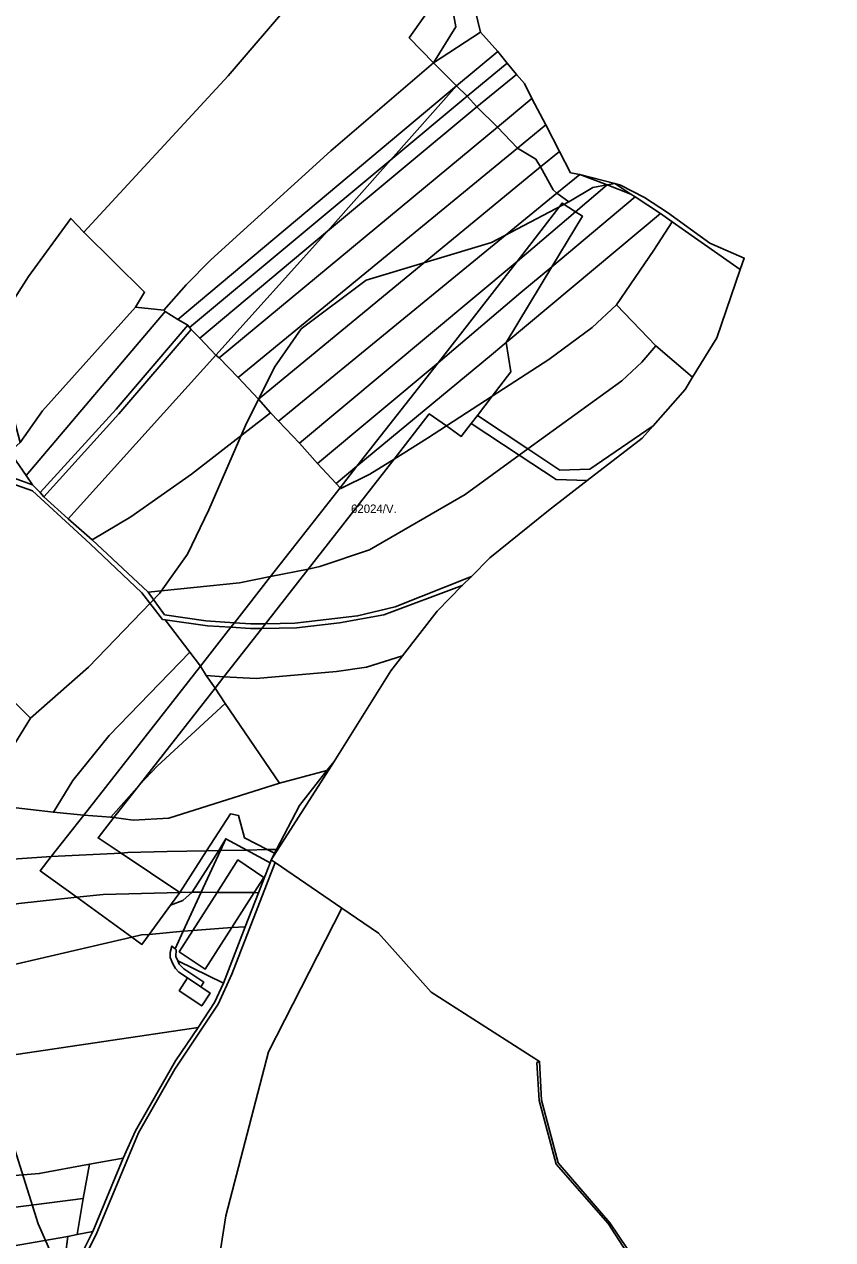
# Model space of a CAD drawing. Extents: x -521261 to -517465, y -1182764 to -1179456.
# Drawn here: x -518915 to -518441, y -1181121 to -1180410 of the extents above; entities that cross this region are included whole.
import ezdxf

# ---------------------------------------------------------------- set-up
doc = ezdxf.new("R2010")
doc.units = 0
for name, color, linetype in [('95560013', 7, 'Continuous'), ('95610013', 7, 'Continuous'), ('95620013', 7, 'Continuous'), ('95640013', 7, 'Continuous'), ('95660013', 7, 'Continuous')]:
    doc.layers.add(name, color=color, linetype=linetype)

msp = doc.modelspace()

# ---------------------------------------------------------------- linework, layer by layer
at = {"layer": '95560013'}
for points in [[(-518924.13, -1180356.64), (-518872.62, -1180293.06), (-518794.77, -1180326.6), (-518776.93, -1180333.89), (-518730.54, -1180354.36), (-518737.91, -1180365.66), (-518757.62, -1180395.93), (-518795.16, -1180439.81), (-518879.8, -1180531.46), (-518887.35, -1180523.29), (-518912.15, -1180557.37), (-518933.81, -1180591.04)], [(-518940.14, -1180668.41), (-518909.75, -1180679.28), (-518905.3, -1180683.88), (-518903.07, -1180686.29), (-518888.87, -1180699.33), (-518874.82, -1180711.46), (-518842.13, -1180742.2), (-518832.43, -1180755.5), (-518808.37, -1180758.98), (-518791.61, -1180760.13), (-518793.68, -1180762.77), (-518807.33, -1180761.84), (-518832.03, -1180758.37), (-518833.61, -1180758.15), (-518845.74, -1180742.65), (-518875.99, -1180713.85), (-518909.82, -1180682.93), (-518941.97, -1180671.51)], [(-518978.45, -1180973.7), (-518851.55, -1180944.12), (-518845.75, -1180948.41), (-518841.44, -1180942.57), (-518821.48, -1180940.76), (-518826.2, -1180951.04), (-518828.15, -1180949.41), (-518829.25, -1180953.11), (-518829.1, -1180956.12), (-518827.68, -1180959.91), (-518826.16, -1180962.51), (-518824.07, -1180964.69), (-518819.03, -1180968), (-518823.9, -1180975.55), (-518810.67, -1180984.43), (-518805.82, -1180976.97), (-518811.29, -1180973.25), (-518809.55, -1180970.63), (-518821.16, -1180962.79), (-518823.96, -1180960.04), (-518824.79, -1180958.13), (-518797.94, -1180971.15), (-518803.2, -1180982.47), (-518812.84, -1180997.02), (-518923.19, -1181013.55)]]:
    msp.add_lwpolyline(points, dxfattribs=at)
for points in [[(-518678.54, -1180367.65), (-518666.6, -1180385.39), (-518689.17, -1180417.51), (-518675.05, -1180432.18), (-518735.07, -1180483.69), (-518805.34, -1180547.49), (-518819.9, -1180562.16), (-518832.97, -1180577.12), (-518849.54, -1180575.21), (-518844.2, -1180566.48), (-518879.8, -1180531.46), (-518795.16, -1180439.81), (-518757.62, -1180395.93), (-518737.91, -1180365.66)], [(-518661.47, -1180445.76), (-518824.6, -1180582.52), (-518832.02, -1180577.88), (-518832.97, -1180577.12), (-518819.9, -1180562.16), (-518805.34, -1180547.49), (-518735.07, -1180483.69), (-518675.05, -1180432.18)], [(-518699.91, -1180489.02), (-518817.87, -1180587.12), (-518818.82, -1180585.93), (-518824.6, -1180582.52), (-518661.47, -1180445.76)], [(-518661.47, -1180445.76), (-518655.36, -1180451.69), (-518699.91, -1180489.02)], [(-518655.36, -1180451.69), (-518649.56, -1180457.93), (-518737.15, -1180530.77), (-518699.91, -1180489.02)], [(-518649.56, -1180457.93), (-518637.61, -1180469.87), (-518800.45, -1180604.89), (-518802.4, -1180603.39), (-518737.15, -1180530.77)], [(-518637.61, -1180469.87), (-518625.72, -1180482.18), (-518789.34, -1180616.43), (-518800.45, -1180604.89)], [(-518737.15, -1180530.77), (-518811.91, -1180593.48), (-518816.83, -1180588.41), (-518817.87, -1180587.12), (-518699.91, -1180489.02)], [(-518625.72, -1180482.18), (-518615, -1180488.64), (-518612.32, -1180493.17), (-518777.37, -1180629.13), (-518789.34, -1180616.43)], [(-518612.32, -1180493.17), (-518604.91, -1180506.68), (-518602.71, -1180508.55), (-518765.74, -1180642.13), (-518770.51, -1180637.12), (-518777.37, -1180629.13)], [(-518573.33, -1180503.74), (-518568.75, -1180502.95), (-518559.46, -1180509.04)], [(-518581.71, -1180505.17), (-518573.33, -1180503.74), (-518591.76, -1180519.42), (-518599.7, -1180514.3), (-518626.09, -1180548.61), (-518753.51, -1180654.84), (-518765.74, -1180642.13), (-518602.71, -1180508.55), (-518595.68, -1180513.69)], [(-518559.46, -1180509.04), (-518556.82, -1180510.74), (-518605.66, -1180551.61), (-518587.79, -1180521.97), (-518591.76, -1180519.42), (-518573.33, -1180503.74)], [(-518556.82, -1180510.74), (-518542.18, -1180520.39), (-518632.43, -1180595.93), (-518605.66, -1180551.61)], [(-518887.35, -1180523.29), (-518879.8, -1180531.46), (-518844.2, -1180566.48), (-518849.54, -1180575.21), (-518903.85, -1180636.05), (-518917.08, -1180654.6), (-518933.81, -1180591.04), (-518912.15, -1180557.37)], [(-518542.18, -1180520.39), (-518535.18, -1180525.31), (-518546.06, -1180541.94), (-518567.78, -1180573.9), (-518582.1, -1180587.18), (-518607.46, -1180605.9), (-518640.58, -1180627.39), (-518629.68, -1180613.23), (-518632.43, -1180595.93)], [(-518811.91, -1180593.48), (-518737.15, -1180530.77), (-518802.4, -1180603.39)], [(-518546.06, -1180541.94), (-518535.18, -1180525.31), (-518495.38, -1180553.32), (-518509.07, -1180593.32), (-518523.28, -1180616.38), (-518544.8, -1180597.87), (-518567.78, -1180573.9)], [(-518626.09, -1180548.61), (-518633.73, -1180558.55), (-518672.36, -1180607.93), (-518742.91, -1180666.93), (-518753.51, -1180654.84)], [(-518567.78, -1180573.9), (-518544.8, -1180597.87), (-518552.96, -1180607.55), (-518564.8, -1180618.45), (-518619.78, -1180658.29), (-518649.3, -1180638.71), (-518640.58, -1180627.39), (-518607.46, -1180605.9), (-518582.1, -1180587.18)], [(-518832.97, -1180577.12), (-518832.02, -1180577.88), (-518913.54, -1180673.81), (-518923.11, -1180660.01), (-518917.08, -1180654.6), (-518903.85, -1180636.05), (-518849.54, -1180575.21)], [(-518824.6, -1180582.52), (-518818.82, -1180585.93), (-518860.74, -1180635.09), (-518905.3, -1180683.88), (-518909.75, -1180679.28), (-518913.54, -1180673.81), (-518832.02, -1180577.88)], [(-518818.82, -1180585.93), (-518817.87, -1180587.12), (-518816.83, -1180588.41), (-518859.24, -1180637.71), (-518903.07, -1180686.29), (-518905.3, -1180683.88), (-518860.74, -1180635.09)], [(-518811.91, -1180593.48), (-518802.4, -1180603.39), (-518888.87, -1180699.33), (-518903.07, -1180686.29), (-518859.24, -1180637.71), (-518816.83, -1180588.41)], [(-518552.96, -1180607.55), (-518544.8, -1180597.87), (-518523.28, -1180616.38), (-518527.66, -1180623.46), (-518546.41, -1180644.74), (-518583.43, -1180670.18), (-518600.95, -1180670.78), (-518619.78, -1180658.29), (-518564.8, -1180618.45)], [(-518800.45, -1180604.89), (-518789.34, -1180616.43), (-518777.37, -1180629.13), (-518770.51, -1180637.12), (-518816.6, -1180673.12), (-518852.15, -1180698.06), (-518874.82, -1180711.46), (-518888.87, -1180699.33), (-518802.4, -1180603.39)], [(-518742.91, -1180666.93), (-518672.36, -1180607.93), (-518719.82, -1180668.45), (-518731.99, -1180678.56)], [(-518765.74, -1180642.13), (-518753.51, -1180654.84), (-518742.91, -1180666.93), (-518731.99, -1180678.56), (-518729.72, -1180681.1), (-518770.41, -1180733.05), (-518788.67, -1180736.73), (-518842.13, -1180742.2), (-518874.82, -1180711.46), (-518852.15, -1180698.06), (-518816.6, -1180673.12), (-518770.51, -1180637.12)], [(-518677.5, -1180637.82), (-518667.48, -1180644.84), (-518678.55, -1180652.02), (-518698.12, -1180664.22)], [(-518658.73, -1180650.97), (-518652.93, -1180643.43), (-518624.83, -1180661.96), (-518656.52, -1180684.91), (-518712.44, -1180717.37), (-518741.49, -1180727.22), (-518748.4, -1180728.62), (-518698.12, -1180664.22), (-518678.55, -1180652.02), (-518667.48, -1180644.84)], [(-518624.83, -1180661.96), (-518603.24, -1180676.18), (-518584.99, -1180676.84), (-518607.61, -1180694.31), (-518642.03, -1180722.06), (-518652.84, -1180732.99), (-518697.4, -1180750.77), (-518719.41, -1180756.07), (-518756.18, -1180760.39), (-518773.42, -1180760.66), (-518748.4, -1180728.62), (-518741.49, -1180727.22), (-518712.44, -1180717.37), (-518656.52, -1180684.91)], [(-518941.97, -1180671.51), (-518909.82, -1180682.93), (-518875.99, -1180713.85), (-518845.74, -1180742.65), (-518833.61, -1180758.15), (-518832.03, -1180758.37), (-518817.62, -1180777.25), (-518864.92, -1180826.18), (-518886.25, -1180852.47), (-518897.52, -1180871.08), (-518951.62, -1180864.77), (-518997.23, -1180861.95), (-519002.07, -1180861.48), (-519002.23, -1180837.59), (-518996.34, -1180802.27), (-518975.66, -1180727.8), (-518956.42, -1180694.36)], [(-518731.99, -1180678.56), (-518719.82, -1180668.45), (-518729.72, -1180681.1)], [(-518788.67, -1180736.73), (-518770.41, -1180733.05), (-518791.61, -1180760.13), (-518808.37, -1180758.98), (-518832.43, -1180755.5), (-518842.13, -1180742.2)], [(-518658.13, -1180738.33), (-518704.02, -1180755.44), (-518729.94, -1180760.13), (-518755.27, -1180762.98), (-518775.57, -1180763.41), (-518773.42, -1180760.66), (-518756.18, -1180760.39), (-518719.41, -1180756.07), (-518697.4, -1180750.77), (-518652.84, -1180732.99)], [(-518672.88, -1180753.24), (-518693.17, -1180779.5), (-518714.15, -1180786.05), (-518731.71, -1180788.65), (-518778.88, -1180792.76), (-518797.69, -1180791.72), (-518775.57, -1180763.41), (-518755.27, -1180762.98), (-518729.94, -1180760.13), (-518704.02, -1180755.44), (-518658.13, -1180738.33)], [(-518832.03, -1180758.37), (-518807.33, -1180761.84), (-518793.68, -1180762.77), (-518811.46, -1180785.47), (-518817.62, -1180777.25)], [(-518817.62, -1180777.25), (-518811.46, -1180785.47), (-518879.81, -1180872.74), (-518897.52, -1180871.08), (-518886.25, -1180852.47), (-518864.92, -1180826.18)], [(-518714.15, -1180786.05), (-518693.17, -1180779.5), (-518699.96, -1180788.29), (-518733.13, -1180841.32), (-518737.39, -1180846.67), (-518765.13, -1180854.02), (-518796.95, -1180807.29), (-518802.83, -1180798.37), (-518797.69, -1180791.72), (-518778.88, -1180792.76), (-518731.71, -1180788.65)], [(-518802.83, -1180798.37), (-518796.95, -1180807.29), (-518836.89, -1180844.01), (-518847.08, -1180854.98)], [(-518796.95, -1180807.29), (-518765.13, -1180854.02), (-518830.06, -1180874.56), (-518850.77, -1180875.63), (-518862.16, -1180874.22), (-518847.08, -1180854.98), (-518836.89, -1180844.01)], [(-518765.13, -1180854.02), (-518737.39, -1180846.67), (-518753.55, -1180867.09), (-518766.86, -1180892.78), (-518772.34, -1180892.89), (-518785.65, -1180886.11), (-518789.09, -1180873.05), (-518793.95, -1180872.06), (-518807.86, -1180893.62), (-518830.94, -1180894.09), (-518853.97, -1180894.54), (-518857.86, -1180895.06), (-518871.4, -1180886.12), (-518862.16, -1180874.22), (-518850.77, -1180875.63), (-518830.06, -1180874.56)], [(-518997.23, -1180861.95), (-518951.62, -1180864.77), (-518897.52, -1180871.08), (-518879.81, -1180872.74), (-518898.78, -1180896.9), (-518930.07, -1180899.02), (-518986.46, -1180908.17)], [(-518796.66, -1180886.59), (-518799.81, -1180893.46), (-518800.74, -1180893.47)], [(-518830.94, -1180894.09), (-518807.86, -1180893.62), (-518823.56, -1180917.96), (-518857.86, -1180895.06), (-518853.97, -1180894.54)], [(-518800.74, -1180893.47), (-518799.81, -1180893.46), (-518810.97, -1180917.8), (-518816.21, -1180917.75)], [(-518772.34, -1180892.89), (-518766.86, -1180892.78), (-518768.05, -1180895.07)], [(-518930.07, -1180899.02), (-518898.78, -1180896.9), (-518905.31, -1180905.29), (-518883.79, -1180920.87), (-518917.86, -1180924.58), (-518979.29, -1180935.1), (-518986.46, -1180908.17)], [(-518767.65, -1180900.49), (-518728.61, -1180927.2), (-518771.62, -1181011.43), (-518796.51, -1181107.45), (-518799.71, -1181127.22), (-518796.94, -1181166.4), (-518785.42, -1181185.66), (-518785.86, -1181197.97), (-518905.05, -1181214.06), (-518893.06, -1181189.28), (-518884.51, -1181142.36), (-518872.03, -1181117.32), (-518847.82, -1181058.73), (-518826.41, -1181021.47), (-518801.1, -1180983.45), (-518793.02, -1180965.88)], [(-518883.79, -1180920.87), (-518851.55, -1180944.12), (-518978.45, -1180973.7), (-518988.33, -1180936.99), (-518979.29, -1180935.1), (-518917.86, -1180924.58)], [(-518810.97, -1180917.8), (-518821.48, -1180940.76), (-518841.44, -1180942.57), (-518829, -1180925.44), (-518821.68, -1180922.72), (-518816.21, -1180917.75)], [(-518812.84, -1180997.02), (-518826.01, -1181016.52), (-518849.41, -1181057.59), (-518856.76, -1181073.68), (-518876.41, -1181077.08), (-518905.87, -1181082.66), (-518981.74, -1181088.87), (-519025.58, -1181089.49), (-519045.75, -1181037.98), (-518961.94, -1181020.33), (-518923.19, -1181013.55)], [(-518905.87, -1181082.66), (-518876.41, -1181077.08), (-518880.14, -1181097.21), (-519012.49, -1181114.11), (-519025.58, -1181089.49), (-518981.74, -1181088.87)], [(-518876.41, -1181077.08), (-518856.76, -1181073.68), (-518874.47, -1181116.54), (-518883.71, -1181118.34), (-518880.14, -1181097.21)], [(-519012.49, -1181114.11), (-518880.14, -1181097.21), (-518883.71, -1181118.34), (-518889.2, -1181119.44), (-518999.4, -1181138.6)], [(-518889.2, -1181119.44), (-518895.9, -1181172.24), (-518899.2, -1181195.41), (-518905.82, -1181208.56), (-518929.63, -1181216.79), (-519012.63, -1181230.94), (-519025, -1181221.11), (-519055.7, -1181212.28), (-519095.79, -1181214.24), (-519111.04, -1181157.52), (-519105.92, -1181156.17), (-519067.69, -1181158.36), (-519018.65, -1181142.26), (-518999.4, -1181138.6)], [(-518883.71, -1181118.34), (-518874.47, -1181116.54), (-518887.13, -1181141.85), (-518895.79, -1181189.08), (-518899.2, -1181195.41), (-518895.9, -1181172.24), (-518889.2, -1181119.44)]]:
    msp.add_lwpolyline(points, close=True, dxfattribs=at)
at = {"layer": '95610013'}
msp.add_lwpolyline([(-518661.93, -1180411.14), (-518675.05, -1180432.18), (-518689.17, -1180417.51), (-518666.6, -1180385.39)], close=True, dxfattribs=at)
at = {"layer": '95620013'}
for points in [[(-518712.53, -1180327.88), (-518703.81, -1180314.81), (-518665.78, -1180361.68), (-518655.44, -1180381.08), (-518647.53, -1180414.17), (-518675.05, -1180432.18), (-518661.93, -1180411.14), (-518666.6, -1180385.39), (-518678.54, -1180367.65)], [(-518637.32, -1180425.55), (-518661.47, -1180445.76), (-518675.05, -1180432.18), (-518647.53, -1180414.17)], [(-518631.95, -1180432.51), (-518655.36, -1180451.69), (-518661.47, -1180445.76), (-518637.32, -1180425.55)], [(-518626.32, -1180439.08), (-518649.56, -1180457.93), (-518655.36, -1180451.69), (-518631.95, -1180432.51)], [(-518621.78, -1180444.3), (-518617.44, -1180453.19), (-518637.61, -1180469.87), (-518649.56, -1180457.93), (-518626.32, -1180439.08)], [(-518609.3, -1180468.45), (-518625.72, -1180482.18), (-518637.61, -1180469.87), (-518617.44, -1180453.19)], [(-518609.3, -1180468.45), (-518601.16, -1180484.23), (-518612.32, -1180493.17), (-518615, -1180488.64), (-518625.72, -1180482.18)], [(-518601.16, -1180484.23), (-518594.75, -1180496.62), (-518589.35, -1180497.6), (-518602.71, -1180508.55), (-518604.91, -1180506.68), (-518612.32, -1180493.17)], [(-518573.33, -1180503.74), (-518581.71, -1180505.17), (-518595.68, -1180513.69), (-518602.71, -1180508.55), (-518589.35, -1180497.6)], [(-518568.75, -1180502.95), (-518573.33, -1180503.74), (-518589.35, -1180497.6)]]:
    msp.add_lwpolyline(points, close=True, dxfattribs=at)
msp.add_lwpolyline([(-518799.71, -1181127.22), (-518796.51, -1181107.45), (-518771.62, -1181011.43), (-518728.61, -1180927.2), (-518707.17, -1180941.87), (-518676.44, -1180976.47), (-518612.92, -1181016.94), (-518614.4, -1181017.6), (-518613.17, -1181039.84), (-518603.1, -1181077.1), (-518572.75, -1181111.95), (-518562.06, -1181128.41)], dxfattribs=at)
at = {"layer": '95640013'}
for points in [[(-518565.5, -1180503.79), (-518551.48, -1180511.06), (-518538.07, -1180519.79), (-518513.23, -1180537.84), (-518493.09, -1180546.62), (-518495.38, -1180553.32), (-518535.18, -1180525.31), (-518542.18, -1180520.39), (-518556.82, -1180510.74), (-518559.46, -1180509.04), (-518568.75, -1180502.95)], [(-518599.7, -1180514.3), (-518591.76, -1180519.42), (-518626.09, -1180548.61)], [(-518591.76, -1180519.42), (-518587.79, -1180521.97), (-518605.66, -1180551.61), (-518623.77, -1180566.7), (-518672.36, -1180607.93), (-518633.73, -1180558.55), (-518626.09, -1180548.61)], [(-518605.66, -1180551.61), (-518632.43, -1180595.93), (-518641, -1180603.15), (-518719.82, -1180668.45), (-518672.36, -1180607.93), (-518623.77, -1180566.7)], [(-518632.43, -1180595.93), (-518629.68, -1180613.23), (-518640.58, -1180627.39), (-518667.48, -1180644.84), (-518677.5, -1180637.82), (-518698.12, -1180664.22), (-518712.25, -1180673.04), (-518729.33, -1180681.52), (-518729.72, -1180681.1), (-518719.82, -1180668.45), (-518641, -1180603.15)], [(-518649.3, -1180638.71), (-518652.93, -1180643.43), (-518658.73, -1180650.97), (-518667.48, -1180644.84), (-518640.58, -1180627.39)], [(-518652.93, -1180643.43), (-518649.3, -1180638.71), (-518619.78, -1180658.29), (-518624.83, -1180661.96)], [(-518552.75, -1180651.93), (-518584.99, -1180676.84), (-518603.24, -1180676.18), (-518624.83, -1180661.96), (-518619.78, -1180658.29), (-518600.95, -1180670.78), (-518583.43, -1180670.18), (-518546.41, -1180644.74)], [(-518932.61, -1180657.78), (-518925.35, -1180647.03), (-518923.11, -1180660.01), (-518913.54, -1180673.81), (-518909.75, -1180679.28), (-518940.14, -1180668.41)], [(-518698.12, -1180664.22), (-518748.4, -1180728.62), (-518770.41, -1180733.05), (-518729.72, -1180681.1), (-518729.33, -1180681.52), (-518712.25, -1180673.04)], [(-518770.41, -1180733.05), (-518748.4, -1180728.62), (-518773.42, -1180760.66), (-518782.04, -1180760.79), (-518791.61, -1180760.13)], [(-518782.22, -1180763.55), (-518775.57, -1180763.41), (-518797.69, -1180791.72), (-518808.06, -1180790.9), (-518811.46, -1180785.47), (-518793.68, -1180762.77)], [(-518782.04, -1180760.79), (-518773.42, -1180760.66), (-518775.57, -1180763.41), (-518782.22, -1180763.55), (-518793.68, -1180762.77), (-518791.61, -1180760.13)], [(-518811.46, -1180785.47), (-518808.06, -1180790.9), (-518802.83, -1180798.37), (-518847.08, -1180854.98), (-518863.98, -1180874.02), (-518879.81, -1180872.74)], [(-518808.06, -1180790.9), (-518797.69, -1180791.72), (-518802.83, -1180798.37)], [(-518737.39, -1180846.67), (-518733.13, -1180841.32), (-518770.01, -1180898.85), (-518768.05, -1180895.07), (-518766.86, -1180892.78), (-518753.55, -1180867.09)], [(-518847.08, -1180854.98), (-518862.16, -1180874.22), (-518863.98, -1180874.02)], [(-518879.81, -1180872.74), (-518863.98, -1180874.02), (-518862.16, -1180874.22), (-518871.4, -1180886.12), (-518857.86, -1180895.06), (-518898.78, -1180896.9)], [(-518789.09, -1180873.05), (-518785.65, -1180886.11), (-518772.34, -1180892.89), (-518784.32, -1180893.28), (-518796.66, -1180886.59), (-518800.74, -1180893.47), (-518807.86, -1180893.62), (-518793.95, -1180872.06)], [(-518784.32, -1180893.28), (-518799.81, -1180893.46), (-518796.66, -1180886.59)], [(-518807.86, -1180893.62), (-518800.74, -1180893.47), (-518816.21, -1180917.75), (-518823.56, -1180917.96)], [(-518799.81, -1180893.46), (-518784.32, -1180893.28), (-518770.69, -1180900.6), (-518777.5, -1180918.25), (-518780.03, -1180918.11), (-518774.32, -1180909.18), (-518789.53, -1180899.01), (-518801.74, -1180917.95), (-518810.97, -1180917.8)], [(-518784.32, -1180893.28), (-518772.34, -1180892.89), (-518768.05, -1180895.07), (-518770.01, -1180898.85), (-518770.69, -1180900.6)], [(-518898.78, -1180896.9), (-518857.86, -1180895.06), (-518823.56, -1180917.96), (-518868.41, -1180919.2), (-518883.79, -1180920.87), (-518905.31, -1180905.29)], [(-518789.53, -1180899.01), (-518774.32, -1180909.18), (-518780.03, -1180918.11), (-518801.74, -1180917.95)], [(-518868.41, -1180919.2), (-518823.56, -1180917.96), (-518829, -1180925.44), (-518841.44, -1180942.57), (-518846.06, -1180942.9), (-518851.55, -1180944.12), (-518883.79, -1180920.87)], [(-518816.21, -1180917.75), (-518821.68, -1180922.72), (-518829, -1180925.44), (-518823.56, -1180917.96)], [(-518801.74, -1180917.95), (-518816.01, -1180940.35), (-518821.48, -1180940.76), (-518810.97, -1180917.8)], [(-518780.03, -1180918.11), (-518793.11, -1180938.56), (-518816.01, -1180940.35), (-518801.74, -1180917.95)], [(-518777.5, -1180918.25), (-518785.21, -1180938.18), (-518793.11, -1180938.56), (-518780.03, -1180918.11)], [(-518846.06, -1180942.9), (-518841.44, -1180942.57), (-518845.75, -1180948.41), (-518851.55, -1180944.12)], [(-518793.11, -1180938.56), (-518785.21, -1180938.18), (-518797.94, -1180971.15), (-518824.79, -1180958.13), (-518825.92, -1180955.48), (-518825.59, -1180951.54), (-518826.2, -1180951.04), (-518821.48, -1180940.76), (-518816.01, -1180940.35), (-518823.87, -1180952.7), (-518808.66, -1180962.88)], [(-518816.01, -1180940.35), (-518793.11, -1180938.56), (-518808.66, -1180962.88), (-518823.87, -1180952.7)], [(-518826.2, -1180951.04), (-518825.59, -1180951.54), (-518825.92, -1180955.48), (-518824.79, -1180958.13), (-518823.96, -1180960.04), (-518821.16, -1180962.79), (-518809.55, -1180970.63), (-518811.29, -1180973.25), (-518819.03, -1180968), (-518824.07, -1180964.69), (-518826.16, -1180962.51), (-518827.68, -1180959.91), (-518829.1, -1180956.12), (-518829.25, -1180953.11), (-518828.15, -1180949.41)], [(-518811.29, -1180973.25), (-518805.82, -1180976.97), (-518810.67, -1180984.43), (-518823.9, -1180975.55), (-518819.03, -1180968)], [(-518612.92, -1181016.94), (-518611.72, -1181039.62), (-518601.93, -1181076.25), (-518571.79, -1181111.44), (-518561.65, -1181126.57), (-518556.81, -1181133.74), (-518522.41, -1181184.93), (-518521.66, -1181185.76), (-518503.98, -1181205.23), (-518492.13, -1181218.29), (-518471.48, -1181251.81), (-518441.26, -1181279.93), (-518468.13, -1181260.3), (-518490.58, -1181233.66), (-518508.25, -1181210.43), (-518524.34, -1181186.8), (-518557.39, -1181136.36), (-518562.06, -1181128.41), (-518572.75, -1181111.95), (-518603.1, -1181077.1), (-518613.17, -1181039.84), (-518614.4, -1181017.6)]]:
    msp.add_lwpolyline(points, close=True, dxfattribs=at)
msp.add_lwpolyline([(-518887.13, -1181141.85), (-518874.47, -1181116.54), (-518856.76, -1181073.68), (-518849.41, -1181057.59), (-518826.01, -1181016.52), (-518812.84, -1180997.02), (-518803.2, -1180982.47), (-518797.94, -1180971.15), (-518785.21, -1180938.18), (-518777.5, -1180918.25), (-518770.69, -1180900.6), (-518770.01, -1180898.85), (-518767.65, -1180900.49), (-518793.02, -1180965.88), (-518801.1, -1180983.45), (-518826.41, -1181021.47), (-518847.82, -1181058.73), (-518872.03, -1181117.32), (-518884.51, -1181142.36)], dxfattribs=at)
at = {"layer": '95660013'}
for points in [[(-518655.44, -1180381.08), (-518647.53, -1180414.17), (-518637.32, -1180425.55), (-518631.95, -1180432.51), (-518626.32, -1180439.08), (-518621.78, -1180444.3), (-518617.44, -1180453.19), (-518609.3, -1180468.45), (-518601.16, -1180484.23), (-518594.75, -1180496.62), (-518589.35, -1180497.6), (-518568.75, -1180502.95), (-518573.33, -1180503.74), (-518581.71, -1180505.17), (-518595.68, -1180513.69), (-518602.71, -1180508.55), (-518604.91, -1180506.68), (-518612.32, -1180493.17), (-518615, -1180488.64), (-518625.72, -1180482.18), (-518637.61, -1180469.87), (-518649.56, -1180457.93), (-518655.36, -1180451.69), (-518661.47, -1180445.76), (-518675.05, -1180432.18), (-518661.93, -1180411.14), (-518666.6, -1180385.39)], [(-518666.6, -1180385.39), (-518661.93, -1180411.14), (-518675.05, -1180432.18), (-518661.47, -1180445.76), (-518655.36, -1180451.69), (-518649.56, -1180457.93), (-518637.61, -1180469.87), (-518625.72, -1180482.18), (-518615, -1180488.64), (-518612.32, -1180493.17), (-518604.91, -1180506.68), (-518602.71, -1180508.55), (-518595.68, -1180513.69), (-518641, -1180537.5), (-518714.5, -1180559.5), (-518752.5, -1180588), (-518768, -1180610.5), (-518785, -1180644.5), (-518806.5, -1180694), (-518819, -1180720), (-518835.5, -1180743), (-518877, -1180786), (-518911, -1180816), (-518931, -1180796)], [(-518928, -1180843.5), (-518911, -1180816), (-518877, -1180786), (-518835.5, -1180743), (-518819, -1180720), (-518806.5, -1180694), (-518785, -1180644.5), (-518768, -1180610.5), (-518752.5, -1180588), (-518714.5, -1180559.5), (-518641, -1180537.5), (-518595.68, -1180513.69), (-518581.71, -1180505.17), (-518573.33, -1180503.74), (-518568.75, -1180502.95), (-518565.5, -1180503.79), (-518551.48, -1180511.06), (-518538.07, -1180519.79), (-518513.23, -1180537.84), (-518493.09, -1180546.62), (-518495.38, -1180553.32), (-518509.07, -1180593.32), (-518523.28, -1180616.38), (-518527.66, -1180623.46), (-518546.41, -1180644.74), (-518552.75, -1180651.93), (-518584.99, -1180676.84), (-518607.61, -1180694.31), (-518642.03, -1180722.06), (-518652.84, -1180732.99), (-518658.13, -1180738.33), (-518672.88, -1180753.24), (-518693.17, -1180779.5), (-518699.96, -1180788.29), (-518733.13, -1180841.32), (-518770.01, -1180898.85), (-518767.65, -1180900.49), (-518728.61, -1180927.2), (-518771.62, -1181011.43), (-518796.51, -1181107.45), (-518799.71, -1181127.22)], [(-518931, -1180796), (-518911, -1180816), (-518928, -1180843.5)], [(-518799.71, -1181127.22), (-518796.51, -1181107.45), (-518771.62, -1181011.43), (-518728.61, -1180927.2), (-518707.17, -1180941.87), (-518676.44, -1180976.47), (-518612.92, -1181016.94), (-518611.72, -1181039.62), (-518601.93, -1181076.25), (-518571.79, -1181111.44), (-518561.65, -1181126.57)], [(-518888, -1181154), (-518906.5, -1181112), (-518950, -1180974)], [(-518950, -1180974), (-518906.5, -1181112), (-518888, -1181154)]]:
    msp.add_lwpolyline(points, dxfattribs=at)

# ---------------------------------------------------------------- texts
msp.add_text('62024/V.', height=5, rotation=0, dxfattribs=at).set_placement((-518723.3, -1180695.85))

doc.saveas('drawing.dxf')
